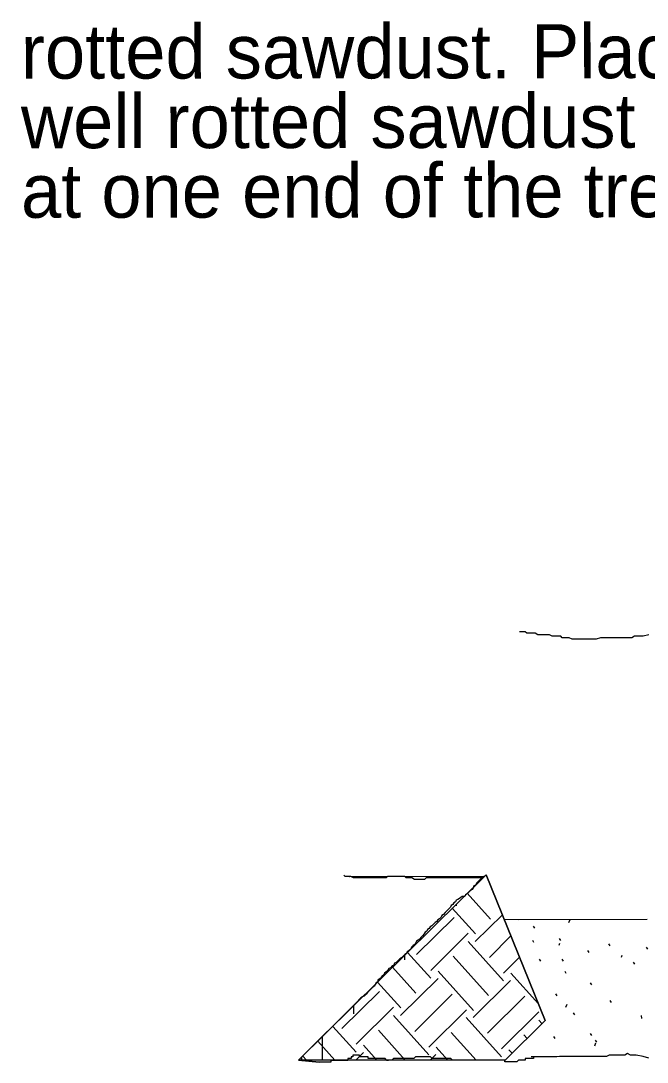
# Model space of a CAD drawing. Extents: x 816132 to 817815, y 885694 to 886789.
# Drawn here: x 816289.5 to 816367.2, y 886208.6 to 886337.7 of the extents above; entities that cross this region are included whole.
import ezdxf

# ---------------------------------------------------------------- set-up
doc = ezdxf.new("R2010")
doc.units = 0
doc.layers.add('Silt Fence Coir Fiber Wattle Break Detail CELL', color=7, linetype='Continuous')

msp = doc.modelspace()

# ---------------------------------------------------------------- linework, layer by layer
at = {"layer": 'Silt Fence Coir Fiber Wattle Break Detail CELL'}
for p, q in [((816323.98, 886208.89), (816347.24, 886231.89)), ((816346.97, 886231.66), (816330.26, 886231.64)), ((816346.99, 886231.65), (816330.28, 886231.64)), ((816346.99, 886231.65), (816330.28, 886231.64)), ((816347.24, 886231.89), (816354.56, 886213.8)), ((816354.56, 886213.8), (816347.24, 886231.89)), ((816347.78, 886226.38), (816344.9, 886229.58)), ((816345.92, 886224.54), (816343.04, 886227.74)), ((816343.54, 886228.24), (816343.54, 886228.01)), ((816338.61, 886221.98), (816343.26, 886226.59)), ((816345.89, 886223.59), (816349.25, 886226.92)), ((816349.49, 886226.34), (816367.2, 886226.36)), ((816351.24, 886226.34), (816367.21, 886226.36)), ((816351.24, 886226.34), (816367.21, 886226.36)), ((816357.5, 886225.97), (816357.66, 886226.35)), ((816367.2, 886226.31), (816367.2, 886226.31)), ((816367.2, 886226.31), (816367.2, 886226.31)), ((816340.37, 886220.03), (816345.01, 886224.64)), ((816353.09, 886225.49), (816353.25, 886225.24)), ((816349.38, 886218.75), (816344.99, 886223.62)), ((816347.65, 886221.64), (816350.32, 886224.29)), ((816352.97, 886223.78), (816353.13, 886223.54)), ((816356.28, 886223.14), (816356.39, 886223.39)), ((816356.31, 886223.98), (816356.46, 886223.73)), ((816362.43, 886223.33), (816362.58, 886223.08)), ((816340.37, 886219.05), (816337.49, 886222.25)), ((816359.83, 886222.51), (816359.99, 886222.26)), ((816364.03, 886221.67), (816364.13, 886221.92)), ((816367.08, 886222.89), (816367.24, 886222.64)), ((816337.11, 886221.88), (816337.11, 886221.35)), ((816347.52, 886216.91), (816343.13, 886221.78)), ((816349.4, 886219.7), (816351.38, 886221.66)), ((816353.81, 886221.42), (816353.97, 886221.17)), ((816356.63, 886221.42), (816356.78, 886221.17)), ((816365.46, 886221.03), (816365.62, 886220.78)), ((816338.52, 886217.21), (816335.63, 886220.41)), ((816345.66, 886215.06), (816341.27, 886219.94)), ((816353.72, 886215.88), (816350.31, 886219.67)), ((816356.98, 886219.94), (816357.14, 886219.7)), ((816336.66, 886215.37), (816333.77, 886218.57)), ((816336.63, 886214.42), (816341.28, 886219.02)), ((816345.64, 886214.18), (816350.28, 886218.79)), ((816360.15, 886218.47), (816360.31, 886218.22)), ((816329.35, 886212.81), (816334, 886217.41)), ((816338.39, 886212.47), (816343.03, 886217.07)), ((816347.39, 886212.23), (816352.04, 886216.84)), ((816355.85, 886217.13), (816356.01, 886216.89)), ((816330.77, 886215.61), (816330.77, 886214.64)), ((816331.11, 886210.86), (816335.76, 886215.46)), ((816357.11, 886215.47), (816357.27, 886215.85)), ((816362.58, 886216.28), (816362.74, 886216.03)), ((816340.12, 886209.57), (816335.73, 886214.44)), ((816340.15, 886210.52), (816344.79, 886215.12)), ((816349.15, 886209.3), (816344.77, 886214.18)), ((816349.15, 886210.29), (816353.79, 886214.89)), ((816358.04, 886214.77), (816358.2, 886214.53)), ((816366.48, 886214.44), (816366.52, 886214.07)), ((816331.12, 886209.87), (816328.22, 886213.09)), ((816354.56, 886213.8), (816349.59, 886208.91)), ((816354.58, 886213.8), (816349.61, 886208.91)), ((816354.58, 886213.8), (816349.61, 886208.91)), ((816354.17, 886213.42), (816353.77, 886213.87)), ((816326.89, 886211.77), (816326.89, 886208.89)), ((816337.21, 886208.9), (816333.87, 886212.6)), ((816345.99, 886208.91), (816342.91, 886212.33)), ((816352.31, 886211.59), (816351.91, 886212.03)), ((816355.58, 886211.82), (816355.74, 886211.57)), ((816360.15, 886212.19), (816360.31, 886211.94)), ((816328.48, 886208.89), (816326.36, 886211.25)), ((816333.69, 886208.9), (816332.01, 886210.76)), ((816342.48, 886208.91), (816341.05, 886210.49)), ((816360.7, 886210.68), (816360.86, 886211.05)), ((816360.75, 886211.39), (816360.91, 886211.14)), ((816324.34, 886209.25), (816324.34, 886208.89)), ((816324.97, 886208.89), (816324.5, 886209.41)), ((816331.06, 886208.9), (816332.02, 886209.85)), ((816340.31, 886208.9), (816341.02, 886209.61)), ((816350.45, 886209.75), (816350.05, 886210.19)), ((816349.59, 886208.91), (816323.98, 886208.89))]:
    msp.add_line(p, q, dxfattribs=at)
for points in [[(816367.4, 886261.64), (816366.7, 886261.46), (816366.35, 886261.46), (816365.99, 886261.46), (816365.64, 886261.46), (816365.29, 886261.27), (816364.76, 886261.27), (816364.41, 886261.27), (816364.06, 886261.27), (816363.53, 886261.27), (816363.18, 886261.27), (816362.65, 886261.27), (816362.12, 886261.27), (816361.77, 886261.27), (816361.42, 886261.27), (816360.89, 886261.08), (816360.54, 886261.08), (816359.83, 886261.08), (816359.31, 886261.08), (816358.95, 886261.08), (816358.6, 886261.08), (816358.25, 886261.08), (816357.9, 886261.08), (816357.55, 886261.27), (816357.19, 886261.27), (816356.67, 886261.27), (816356.49, 886261.45), (816356.14, 886261.45), (816355.79, 886261.45), (816355.43, 886261.45), (816355.08, 886261.63), (816354.55, 886261.63), (816354.2, 886261.63), (816353.67, 886261.63), (816353.32, 886261.82), (816352.97, 886261.82), (816352.62, 886261.82), (816352.27, 886261.82), (816352.09, 886262), (816351.74, 886262), (816351.39, 886262), (816351.39, 886262)], [(816347.24, 886231.89), (816347.09, 886231.7), (816346.88, 886231.59), (816346.67, 886231.48), (816346.47, 886231.26), (816346.26, 886231.04), (816346.05, 886230.82), (816345.94, 886230.6), (816345.73, 886230.49), (816345.63, 886230.27), (816345.52, 886230.05), (816345.31, 886229.94), (816345.1, 886229.72), (816344.9, 886229.5), (816344.69, 886229.39), (816344.58, 886229.17), (816344.27, 886229.17), (816343.95, 886228.94), (816343.74, 886228.83), (816343.53, 886228.73), (816343.43, 886228.51), (816343.22, 886228.39), (816343.12, 886228.18), (816342.91, 886228.07), (816342.8, 886227.85), (816342.59, 886227.63), (816342.38, 886227.41), (816342.17, 886227.19), (816341.96, 886226.96), (816341.76, 886226.85), (816341.65, 886226.64), (816341.44, 886226.42), (816341.23, 886226.3), (816341.13, 886226.08), (816340.92, 886225.97), (816340.71, 886225.75), (816340.5, 886225.54), (816340.29, 886225.43), (816340.19, 886225.2), (816339.98, 886225.09), (816339.87, 886224.87), (816339.66, 886224.76), (816339.56, 886224.54), (816339.35, 886224.32), (816339.14, 886224.1), (816339.03, 886223.88), (816338.82, 886223.77), (816338.62, 886223.66), (816338.51, 886223.44), (816338.41, 886223.22), (816338.2, 886223.11), (816337.99, 886222.89), (816337.88, 886222.67), (816337.67, 886222.45), (816337.46, 886222.34), (816337.36, 886222.12), (816337.15, 886222.01), (816336.94, 886221.79), (816336.73, 886221.57), (816336.52, 886221.46), (816336.31, 886221.24), (816336.1, 886221.02), (816335.89, 886220.91), (816335.79, 886220.69), (816335.58, 886220.58), (816335.37, 886220.36), (816335.16, 886220.25), (816334.95, 886219.92), (816334.64, 886219.7), (816334.53, 886219.48), (816334.32, 886219.26), (816334.11, 886219.04), (816333.8, 886218.82), (816333.8, 886218.6), (816333.59, 886218.49), (816333.49, 886218.27), (816333.38, 886218.05), (816333.17, 886217.94), (816332.96, 886217.72), (816332.75, 886217.5), (816332.54, 886217.28), (816332.34, 886217.06), (816332.13, 886216.84), (816331.92, 886216.73), (816331.71, 886216.62), (816331.5, 886216.4), (816331.29, 886216.18), (816323.98, 886208.89), (816323.98, 886208.89), (816331.29, 886216.18)], [(816346.99, 886231.65), (816346.47, 886231.5), (816346.11, 886231.5), (816345.76, 886231.5), (816345.41, 886231.5), (816345.06, 886231.5), (816344.7, 886231.49), (816344.35, 886231.49), (816344, 886231.49), (816343.47, 886231.49), (816343.12, 886231.49), (816342.77, 886231.49), (816342.42, 886231.49), (816341.89, 886231.49), (816341.54, 886231.49), (816341.19, 886231.49), (816340.83, 886231.49), (816340.48, 886231.49), (816340.13, 886231.49), (816339.78, 886231.49), (816339.6, 886231.31), (816339.25, 886231.31), (816338.72, 886231.31), (816338.37, 886231.3), (816338.02, 886231.49), (816337.67, 886231.49), (816337.31, 886231.49), (816337.14, 886231.67), (816336.78, 886231.67), (816336.43, 886231.67), (816336.08, 886231.67), (816335.73, 886231.67), (816335.38, 886231.67), (816335.02, 886231.67), (816334.85, 886231.49), (816334.32, 886231.49), (816333.97, 886231.49), (816333.62, 886231.49), (816333.26, 886231.49), (816332.91, 886231.49), (816332.56, 886231.49), (816332.21, 886231.48), (816331.68, 886231.48), (816331.33, 886231.48), (816330.8, 886231.48), (816330.45, 886231.67), (816330.1, 886231.67), (816329.74, 886231.67), (816329.57, 886231.85), (816329.57, 886231.85)], [(816333.02, 886209.09), (816333.02, 886209.09), (816332.81, 886209.09), (816332.6, 886209.09), (816332.6, 886209.31), (816332.39, 886209.31), (816332.18, 886209.31), (816331.97, 886209.31), (816331.76, 886209.31), (816331.55, 886209.31), (816331.55, 886209.53), (816331.34, 886209.53), (816331.14, 886209.53), (816330.93, 886209.53), (816330.72, 886209.53), (816330.72, 886209.31), (816330.51, 886209.31), (816330.51, 886209.09), (816330.3, 886209.09), (816330.09, 886209.09), (816330.09, 886208.87), (816329.88, 886208.87), (816329.67, 886208.87), (816329.46, 886208.87), (816329.25, 886208.87), (816329.04, 886208.87), (816328.83, 886208.87), (816328.62, 886208.87), (816328.41, 886208.87), (816328.2, 886208.87), (816327.99, 886208.87), (816327.99, 886208.65), (816327.78, 886208.65), (816327.57, 886208.65), (816327.37, 886208.65), (816327.16, 886208.65), (816326.95, 886208.65), (816326.74, 886208.65), (816326.53, 886208.65), (816323.98, 886208.89), (816323.98, 886208.89), (816326.53, 886208.65)], [(816353.35, 886209.33), (816353.13, 886209.33), (816353.13, 886209.11), (816352.92, 886209.11), (816352.71, 886209.11), (816352.5, 886209.11), (816352.29, 886209.11), (816352.08, 886209.11), (816352.08, 886208.89), (816351.88, 886208.89), (816351.67, 886208.89), (816351.46, 886208.89), (816351.25, 886208.89), (816351.04, 886208.67), (816350.83, 886208.67), (816350.62, 886208.67), (816350.41, 886208.67), (816350.2, 886208.67), (816349.99, 886208.67), (816349.78, 886208.67), (816349.57, 886208.67), (816349.57, 886208.89), (816349.36, 886208.89), (816349.15, 886208.89), (816348.94, 886208.89), (816348.73, 886208.89), (816348.52, 886208.89), (816348.31, 886208.89), (816348.1, 886208.89), (816347.9, 886208.88), (816347.68, 886208.88), (816347.48, 886208.88), (816347.27, 886208.88), (816347.06, 886208.88), (816346.85, 886208.88), (816346.64, 886208.88), (816346.43, 886208.88), (816346.22, 886208.88), (816346.01, 886208.88), (816345.8, 886208.88), (816345.59, 886208.88), (816345.38, 886208.88), (816345.17, 886208.88), (816344.96, 886208.88), (816344.75, 886208.88), (816344.54, 886208.88), (816344.33, 886208.88), (816344.12, 886208.88), (816343.91, 886208.88), (816343.7, 886208.88), (816343.5, 886208.88), (816343.29, 886208.88), (816343.08, 886208.88), (816342.87, 886209.1), (816342.66, 886209.1), (816342.45, 886209.1), (816342.24, 886209.1), (816342.03, 886209.1), (816341.82, 886209.1), (816341.61, 886209.1), (816341.4, 886209.1), (816341.19, 886209.1), (816340.98, 886209.1), (816340.77, 886209.1), (816340.56, 886209.1), (816340.35, 886209.32), (816340.14, 886209.32), (816339.93, 886209.32), (816339.72, 886209.32), (816339.51, 886209.32), (816339.31, 886209.32), (816339.1, 886209.32), (816338.89, 886209.32), (816338.68, 886209.32), (816338.47, 886209.32), (816338.26, 886209.1), (816338.05, 886209.1), (816337.84, 886209.1), (816337.63, 886209.1), (816337.42, 886209.1), (816337.21, 886209.1), (816337, 886209.1), (816336.79, 886209.1), (816336.58, 886209.1), (816336.37, 886209.1), (816336.16, 886209.09), (816335.95, 886209.1), (816335.74, 886209.1), (816335.54, 886208.88), (816335.33, 886208.88), (816335.12, 886208.87), (816334.91, 886208.87), (816334.7, 886209.09), (816334.49, 886209.09), (816334.28, 886209.09), (816334.07, 886209.09), (816333.86, 886209.09), (816333.65, 886209.09), (816333.44, 886209.09), (816333.23, 886209.09), (816333.02, 886209.09)], [(816367.43, 886209.16), (816366.72, 886209.34), (816365.84, 886209.53), (816365.14, 886209.53), (816364.79, 886209.71), (816364.43, 886209.53), (816364.08, 886209.53), (816363.73, 886209.53), (816363.38, 886209.53), (816362.85, 886209.53), (816362.5, 886209.52), (816362.15, 886209.34), (816361.79, 886209.34), (816361.44, 886209.34), (816360.91, 886209.34), (816360.39, 886209.34), (816359.86, 886209.34), (816359.51, 886209.34), (816359.15, 886209.34), (816358.45, 886209.34), (816357.75, 886209.34), (816357.22, 886209.34), (816356.87, 886209.34), (816356.34, 886209.34), (816355.99, 886209.33), (816355.46, 886209.33), (816354.75, 886209.33), (816354.4, 886209.33), (816353.87, 886209.33), (816353.35, 886209.33), (816352.82, 886209.33)]]:
    msp.add_lwpolyline(points, dxfattribs=at)

# ---------------------------------------------------------------- texts
for s, p in [(' rotted sawdust. Place a 2 inch layer of', (816287.04, 886330.56)), (' well rotted sawdust at a sloping angle', (816287.05, 886321.94)), (' at one end of the trench. ', (816287.06, 886313.32))]:
    msp.add_text(s, height=6.7041, rotation=0.045, dxfattribs=at).set_placement(p)

doc.saveas('drawing.dxf')
